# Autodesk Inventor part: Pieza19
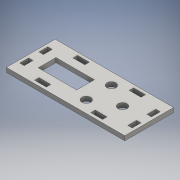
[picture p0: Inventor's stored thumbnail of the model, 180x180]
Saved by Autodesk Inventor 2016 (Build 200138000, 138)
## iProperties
Created: 2016-06
Part Number: Pieza19
Material: Genérico
Document SubType Name: Modeling
Designer: adm
Density: 1 g/cm^3
Appearance: Valor por defecto
Author: adm
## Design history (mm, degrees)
sketch "Boceto1"
  geometry: L1 (35, -11.5)-(-35, 11.5); L2 (-35, -11.5)-(28.913, 9.5); L3 (-40, 16.5)-(40, 16.5); L4 (40, 16.5)-(40, -16.5); L5 (40, -16.5)-(-40, -16.5); L6 (-40, -16.5)-(-40, 16.5); L7 (-15, 14.5)-(-15, 11.5); L8 (-15, -11.5)-(-15, -14.5); L9 (-23, 14.5)-(-23, 11.5); L10 (-23, -11.5)-(-23, -14.5); L11 (23, 14.5)-(23, 11.5); L12 (23, -11.5)-(23, -14.5); L13 (15, 14.5)-(15, 11.5); L14 (15, -11.5)-(15, -14.5); L15 (35, 9.5)-(38, 9.5); L16 (35, 3.5)-(38, 3.5); L17 (35, -3.5)-(38, -3.5); L18 (35, -9.5)-(38, -9.5); L19 (-38, 9.5)-(-35, 9.5); L20 (-38, 3.5)-(-35, 3.5); L21 (-38, -3.5)-(-35, -3.5); L22 (-38, -9.5)-(-35, -9.5); L23 (38, -9.5)-(38, -3.5); L24 (38, 3.5)-(38, 9.5); L25 (35, 9.5)-(35, 3.5); L26 (35, -3.5)-(35, -9.5); L27 (23, 14.5)-(15, 14.5); L28 (-15, 14.5)-(-23, 14.5); L29 (-23, 11.5)-(-15, 11.5); L30 (15, 11.5)-(23, 11.5); L31 (-35, -9.5)-(-35, -3.5); L32 (-35, 3.5)-(-35, 9.5); L33 (-38, 9.5)-(-38, 3.5); L34 (-38, -3.5)-(-38, -9.5); L35 (23, -11.5)-(15, -11.5); L36 (-15, -11.5)-(-23, -11.5); L37 (-23, -14.5)-(-15, -14.5); L38 (15, -14.5)-(23, -14.5); 1 further point
  constraints: 76 end point, 18 parallel, 10 horizontal, 9 perpendicular, 8 vertical, 2 horizontal alignment, 1 midpoint, 1 point on line
  dimensions: "d0" = 70 distance of L1.start L2.start; "d26" = 6 distance of L20.end L19.end; "d27" = 7 distance between parallel lines of L3 L19; "d28" = 6 distance of L16.end L15.end; "d29" = 33 distance between parallel lines of L5 L3; "d30" = 7 distance between parallel lines of L20 L21; "d31" = 7 distance between parallel lines of L5 L22
extrude "Extrusión1" new body sketch "Boceto1" distance "d12" = 3; taper "d13" = 0 deg
sketch "Boceto2"
  geometry: L1 (40, -16.5)-(40, 16.5) reference; L2 (40, 16.5)-(-40, 16.5) reference; L3 (-40, -16.5)-(40, -16.5) reference; L4 (-3, 6)-(-29, 6); L5 (-29, 6)-(-29, -6); L6 (-29, -6)-(-3, -6); L7 (-3, -6)-(-3, 6); L8 (35, 3.5)-(35, 9.5) reference; L9 (35, -3.5)-(35, -9.5) reference; L10 (35, -9.5)-(38, -9.5) reference; L11 (15, -11.5)-(23, -11.5) reference; L12 (-15, -11.5)-(-15, -14.5) reference; C1 r 3 at (22, 0); C2 r 3 at (6, 8.5); C3 r 3 at (6, -8.5); 2 further points
  constraints: 8 end point, 3 centre point, 2 parallel, 1 horizontal, 1 horizontal alignment, 1 midpoint, 1 perpendicular
  dimensions: "d14" = 18 distance from line of C1.centre L1; "d15" = 6 diameter of C1; "d16" = 34 distance from line of L1 C3.centre; "d17" = 34 distance from line of L1 C2.centre; "d18" = 6 diameter of C2; "d19" = 6 diameter of C3; "d20" = 26 distance of L5.end L6.end; "d21" = 12 distance of L6.end L4.start; "d22" = 9 distance from line of C2.centre L7
extrude "Extrusión2" cut sketch "Boceto2" distance "d23" = 3; taper "d24" = 0 deg
node "Sólido1"
other parameters: "d2" = 3, "d3" = 2, "d4" = 8, "d5" = 8, "d6" = 15, "d7" = 15, "d8" = 6, "d9" = 6, "d10" = 3.5, "d11" = 3.5
